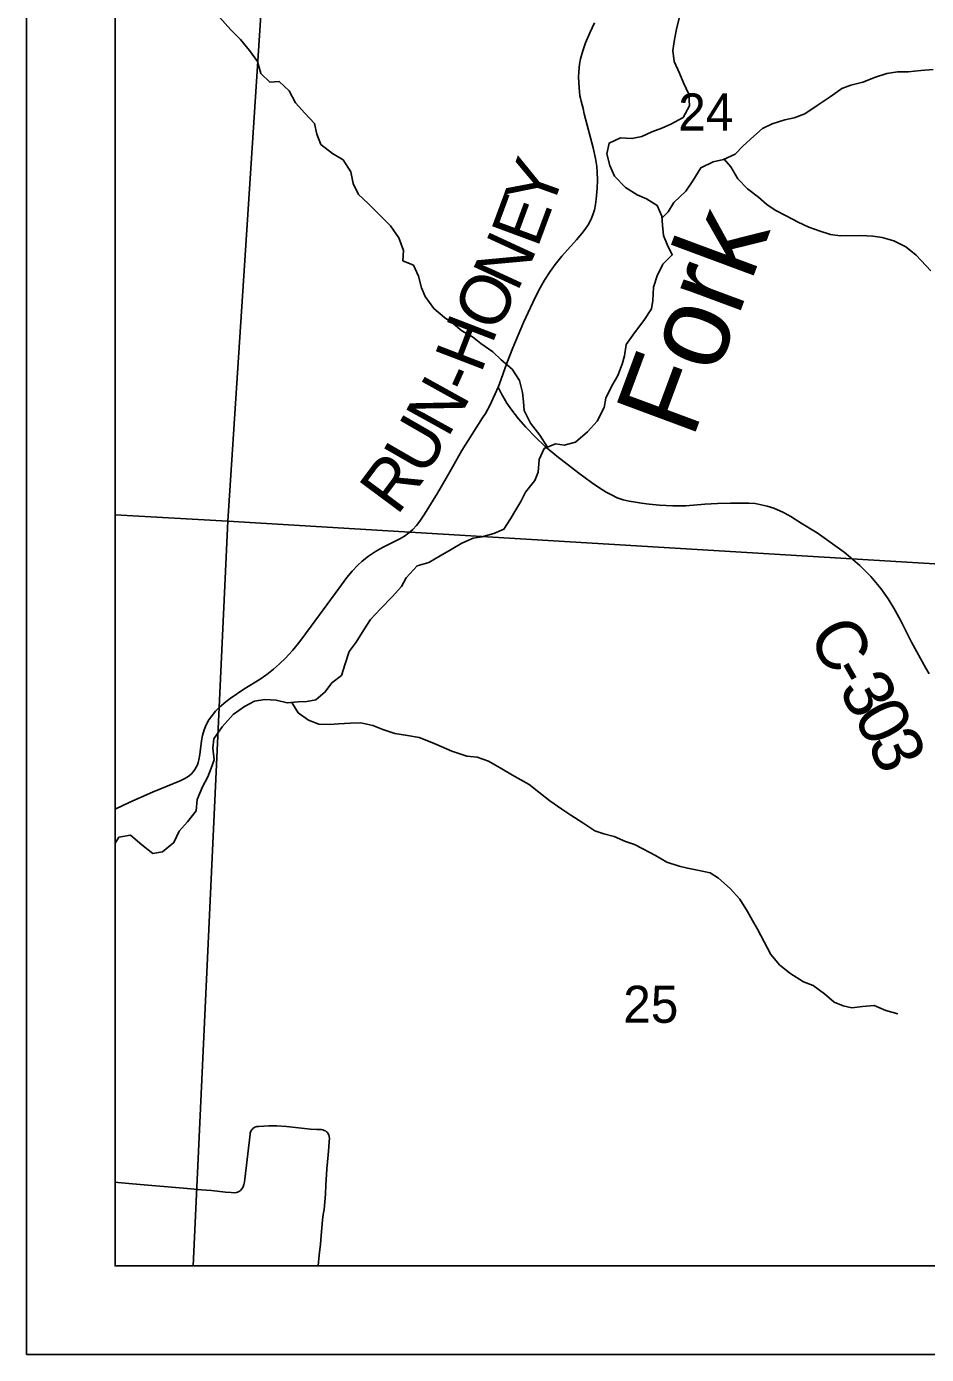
# Model space of a CAD drawing. Extents: x 0 to 34, y 0 to 22.
# Drawn here: x 2 to 3.016, y 14 to 15.5 of the extents above; entities that cross this region are included whole.
import ezdxf

# ---------------------------------------------------------------- set-up
doc = ezdxf.new("R2010")
doc.units = 0
for name, color, linetype in [('GM_X_Corporation', 7, 'Continuous'), ('GM_X_County_Road', 7, 'Continuous'), ('GM_X_County_Road_Text', 7, 'Continuous'), ('GM_X_Major_River', 7, 'Continuous'), ('GM_X_Major_River_Text', 7, 'Continuous'), ('GM_X_Minor_River', 7, 'Continuous'), ('GM_X_Section_Text', 7, 'Continuous'), ('GM_X_Township_Road', 7, 'Continuous'), ('SH_Data', 7, 'Continuous')]:
    doc.layers.add(name, color=color, linetype=linetype)

msp = doc.modelspace()

# ---------------------------------------------------------------- linework, layer by layer
at = {"layer": 'GM_X_Corporation'}
for points in [[(2.1, 19.0816), (2.1, 14.1), (3.1902, 14.1), (3.1919, 14.1255), (3.2339, 14.7735), (3.2844, 15.554), (3.3059, 15.8844), (3.3516, 16.5898), (3.3951, 17.2616), (3.507, 18.9883), (2.9513, 19.0267), (2.509, 19.0572), (2.4972, 19.0545), (2.4649, 19.0567)], [(2.1, 15.9736), (2.1, 14.9482), (2.2272, 14.9411), (2.2939, 15.964)], [(2.2939, 15.964), (3.3089, 15.8803), (3.2437, 14.8797), (2.2272, 14.9411)], [(2.1, 14.9482), (2.1, 14.1), (2.1881, 14.1), (2.2272, 14.9411)], [(2.1881, 14.1), (3.1916, 14.1), (3.2437, 14.8797), (2.2272, 14.9411)]]:
    msp.add_lwpolyline(points, close=True, dxfattribs=at)
at = {"layer": 'GM_X_County_Road'}
for points in [[(2.1, 14.6159), (2.1167, 14.6238), (2.1423, 14.6351), (2.1734, 14.648), (2.1789, 14.6507), (2.1815, 14.6522), (2.184, 14.654), (2.1862, 14.656), (2.1882, 14.6582), (2.19, 14.6606), (2.1916, 14.6632), (2.1929, 14.6659), (2.1939, 14.6687), (2.1947, 14.6717), (2.1957, 14.6777), (2.1976, 14.6932), (2.1987, 14.6993), (2.2005, 14.7054), (2.2029, 14.7112), (2.2059, 14.7168), (2.2095, 14.7219), (2.2135, 14.7268), (2.218, 14.7312), (2.225, 14.7373), (2.2299, 14.741), (2.2455, 14.7513), (2.2638, 14.7629), (2.2701, 14.7672), (2.2715, 14.7682), (2.2787, 14.7739), (2.2857, 14.78), (2.2923, 14.7865), (2.3006, 14.7956), (2.3085, 14.8052), (2.3214, 14.8226), (2.3526, 14.865), (2.3618, 14.8776), (2.3677, 14.8848), (2.3742, 14.8916), (2.3788, 14.8959), (2.3862, 14.9017), (2.394, 14.9068), (2.4021, 14.9114), (2.4215, 14.9211), (2.4268, 14.9242), (2.4317, 14.9279), (2.4362, 14.932), (2.4403, 14.9365), (2.444, 14.9414), (2.4492, 14.949), (2.464, 14.9727), (2.478, 14.9968), (2.4917, 15.0211), (2.5031, 15.0396), (2.5149, 15.0579), (2.5183, 15.063), (2.5228, 15.071), (2.5293, 15.0849), (2.5324, 15.0925), (2.5339, 15.0964), (2.5423, 15.1198), (2.5493, 15.1371), (2.5613, 15.1657), (2.5716, 15.1884), (2.5786, 15.2022), (2.5849, 15.2134), (2.5911, 15.2232), (2.5969, 15.2313), (2.6043, 15.2405), (2.6209, 15.2592), (2.627, 15.2662), (2.6308, 15.271), (2.6342, 15.2761), (2.6372, 15.2815), (2.6395, 15.2871), (2.6412, 15.293), (2.6425, 15.299), (2.6433, 15.3051), (2.6443, 15.3174), (2.6446, 15.3266), (2.6444, 15.3359), (2.6438, 15.3419), (2.6424, 15.3508), (2.6397, 15.3628), (2.6297, 15.4014), (2.6285, 15.4072), (2.6262, 15.4158), (2.6256, 15.4189), (2.6249, 15.4218), (2.6239, 15.4312), (2.6234, 15.4429), (2.6236, 15.4486), (2.6245, 15.4574), (2.6256, 15.4636), (2.6281, 15.4726), (2.6312, 15.4815), (2.636, 15.4929), (2.6413, 15.5042)], [(2.5324, 15.0925), (2.5364, 15.085), (2.5392, 15.0798), (2.5425, 15.0745), (2.5478, 15.0668), (2.5555, 15.057), (2.5637, 15.0475), (2.5746, 15.0362), (2.5855, 15.0256), (2.5989, 15.0146), (2.6237, 14.9955), (2.6379, 14.9849), (2.6464, 14.9793), (2.6547, 14.9739), (2.6604, 14.9709), (2.6671, 14.9676), (2.6736, 14.9654), (2.6805, 14.9638), (2.6876, 14.9626), (2.6945, 14.9614), (2.7031, 14.9604), (2.7148, 14.9593), (2.7299, 14.9585), (2.7445, 14.9585), (2.7659, 14.9603), (2.7804, 14.9611), (2.7948, 14.9617), (2.8072, 14.9617), (2.8158, 14.9616), (2.8227, 14.9611), (2.8294, 14.9598), (2.8362, 14.9582), (2.8439, 14.9559), (2.8546, 14.9512), (2.863, 14.9464), (2.8748, 14.9391), (2.8929, 14.9279), (2.9233, 14.9064), (2.9306, 14.9003), (2.941, 14.8912), (2.9532, 14.8789), (2.9646, 14.8652), (2.9728, 14.8536), (2.9795, 14.843), (2.9869, 14.8293), (2.9993, 14.8047), (3.0156, 14.7753), (3.0192, 14.7687)]]:
    msp.add_lwpolyline(points, dxfattribs=at)
at = {"layer": 'GM_X_Major_River'}
for points in [[(2.5635, 14.9741), (2.5741, 14.987), (2.5778, 14.9965), (2.5789, 15.0109), (2.5845, 15.0235), (2.5974, 15.0284), (2.6072, 15.027), (2.6197, 15.0304), (2.6333, 15.0423), (2.6442, 15.0541), (2.6521, 15.0696), (2.6543, 15.0802), (2.6607, 15.0932), (2.6675, 15.1057), (2.6724, 15.1186), (2.6754, 15.1281), (2.6772, 15.1406), (2.6866, 15.1539), (2.6972, 15.168), (2.7058, 15.1809), (2.7073, 15.1904), (2.708, 15.2056), (2.7121, 15.2185), (2.7185, 15.2314), (2.7291, 15.242), (2.7234, 15.2538), (2.7192, 15.264), (2.718, 15.2757), (2.7172, 15.2859), (2.7122, 15.2977), (2.7001, 15.3052), (2.6895, 15.3097), (2.6762, 15.318), (2.6641, 15.3308), (2.6587, 15.3429), (2.6553, 15.3562), (2.6579, 15.3683), (2.6707, 15.3744), (2.6836, 15.3733), (2.6949, 15.3757), (2.7059, 15.381), (2.7172, 15.3852), (2.7274, 15.3898), (2.7414, 15.3971), (2.7485, 15.4104), (2.7477, 15.4237), (2.742, 15.4365), (2.7374, 15.4471), (2.7313, 15.4603), (2.7298, 15.4728), (2.7316, 15.4854), (2.7342, 15.499), (2.7372, 15.5104)], [(2.1, 14.5774), (2.1043, 14.5843), (2.1175, 14.5867), (2.13, 14.5757), (2.1426, 14.5659), (2.1535, 14.5679), (2.1664, 14.5782), (2.1724, 14.5911), (2.1818, 14.6017), (2.1916, 14.6139), (2.1927, 14.6268), (2.1987, 14.6412), (2.2047, 14.6526), (2.2085, 14.6621), (2.2118, 14.6716), (2.2103, 14.6849), (2.2114, 14.6955), (2.2208, 14.7088), (2.2332, 14.7229), (2.2461, 14.732), (2.2574, 14.7381), (2.2691, 14.7397), (2.282, 14.739), (2.2941, 14.736), (2.3066, 14.7372), (2.3164, 14.7376), (2.3266, 14.7396), (2.3372, 14.7483), (2.3447, 14.7586), (2.3557, 14.767), (2.3598, 14.7799), (2.3643, 14.7939), (2.3722, 14.8046), (2.3809, 14.8183), (2.3884, 14.8301), (2.3997, 14.8422), (2.4129, 14.8556), (2.4235, 14.8674), (2.4287, 14.8772), (2.4412, 14.8906), (2.4544, 14.8944), (2.4672, 14.902), (2.4793, 14.9093), (2.4914, 14.9162), (2.5043, 14.9219), (2.5141, 14.9235), (2.5277, 14.9273), (2.539, 14.9323), (2.5466, 14.9437), (2.5526, 14.954), (2.5582, 14.9635), (2.5635, 14.9741)]]:
    msp.add_lwpolyline(points, dxfattribs=at)
at = {"layer": 'GM_X_Minor_River'}
for p, q in [((2.2305, 15.4964), (2.218, 15.5107)), ((2.2415, 15.4854), (2.2305, 15.4964)), ((2.2518, 15.473), (2.2415, 15.4854)), ((2.2609, 15.4605), (2.2518, 15.473)), ((2.2647, 15.4469), (2.2609, 15.4605)), ((2.2746, 15.4371), (2.2647, 15.4469)), ((2.2852, 15.4379), (2.2746, 15.4371)), ((2.2966, 15.4273), (2.2852, 15.4379)), ((2.3038, 15.4137), (2.2966, 15.4273)), ((2.3141, 15.402), (2.3038, 15.4137)), ((2.3251, 15.3903), (2.3141, 15.402)), ((2.3278, 15.3782), (2.3251, 15.3903)), ((2.3324, 15.3668), (2.3278, 15.3782)), ((2.3453, 15.3567), (2.3324, 15.3668)), ((2.3574, 15.3495), (2.3453, 15.3567)), ((2.3662, 15.3359), (2.3574, 15.3495)), ((2.7877, 15.3502), (2.7953, 15.3416)), ((2.3689, 15.3227), (2.3662, 15.3359)), ((2.7953, 15.3416), (2.8033, 15.328)), ((2.375, 15.3102), (2.3689, 15.3227)), ((2.8033, 15.328), (2.814, 15.3167)), ((2.814, 15.3167), (2.8265, 15.3073)), ((2.3856, 15.3), (2.375, 15.3102)), ((2.411, 15.2747), (2.3856, 15.3)), ((2.8265, 15.3073), (2.836, 15.299)), ((2.836, 15.299), (2.8455, 15.2926)), ((2.8455, 15.2926), (2.8576, 15.2862)), ((2.8576, 15.2862), (2.8713, 15.2791)), ((2.4202, 15.2611), (2.411, 15.2747)), ((2.8713, 15.2791), (2.8834, 15.2734)), ((2.8834, 15.2734), (2.8963, 15.2689)), ((2.4255, 15.2471), (2.4202, 15.2611)), ((2.8963, 15.2689), (2.908, 15.2652)), ((2.908, 15.2652), (2.9186, 15.2637)), ((2.9186, 15.2637), (2.9421, 15.2638)), ((2.9421, 15.2638), (2.9557, 15.2631)), ((2.9557, 15.2631), (2.9663, 15.2617)), ((2.9663, 15.2617), (2.9792, 15.2579)), ((2.9792, 15.2579), (2.9928, 15.2512)), ((2.4248, 15.2354), (2.4255, 15.2471)), ((2.9928, 15.2512), (3.0046, 15.2418)), ((3.0046, 15.2418), (3.0213, 15.224)), ((2.4369, 15.2305), (2.4248, 15.2354)), ((2.4427, 15.218), (2.4369, 15.2305)), ((2.4461, 15.2048), (2.4427, 15.218)), ((2.4503, 15.1949), (2.4461, 15.2048)), ((2.4598, 15.1813), (2.4503, 15.1949)), ((2.472, 15.1711), (2.4598, 15.1813)), ((2.4822, 15.164), (2.472, 15.1711)), ((2.4917, 15.1561), (2.4822, 15.164)), ((2.5035, 15.1493), (2.4917, 15.1561)), ((2.5129, 15.1418), (2.5035, 15.1493)), ((2.5266, 15.1324), (2.5129, 15.1418)), ((2.5361, 15.1233), (2.5266, 15.1324)), ((2.5483, 15.1131), (2.5361, 15.1233)), ((2.5566, 15.1003), (2.5483, 15.1131)), ((2.5601, 15.0866), (2.5566, 15.1003)), ((2.5612, 15.076), (2.5601, 15.0866)), ((2.562, 15.0662), (2.5612, 15.076)), ((2.5689, 15.0518), (2.562, 15.0662)), ((2.5795, 15.0382), (2.5689, 15.0518)), ((2.5884, 15.025), (2.5795, 15.0382)), ((2.2996, 14.7365), (2.3066, 14.7247)), ((2.3066, 14.7247), (2.3184, 14.7164)), ((2.3184, 14.7164), (2.3301, 14.7119)), ((2.3301, 14.7119), (2.3423, 14.7116)), ((2.3423, 14.7116), (2.3521, 14.7124)), ((2.3521, 14.7124), (2.3657, 14.7132)), ((2.3657, 14.7132), (2.3775, 14.7133)), ((2.3775, 14.7133), (2.3911, 14.7103)), ((2.3911, 14.7103), (2.4025, 14.7058)), ((2.4025, 14.7058), (2.4157, 14.7013)), ((2.4157, 14.7013), (2.4301, 14.6991)), ((2.4301, 14.6991), (2.4434, 14.6969)), ((2.4434, 14.6969), (2.4578, 14.6913)), ((2.4578, 14.6913), (2.468, 14.6868)), ((2.468, 14.6868), (2.4801, 14.6815)), ((2.4801, 14.6815), (2.4972, 14.6759)), ((2.4972, 14.6759), (2.5089, 14.6748)), ((2.5089, 14.6748), (2.5218, 14.67)), ((2.5218, 14.67), (2.5366, 14.6613)), ((2.5366, 14.6613), (2.5487, 14.6542)), ((2.5487, 14.6542), (2.5677, 14.6436)), ((2.5677, 14.6436), (2.5783, 14.6353)), ((2.5783, 14.6353), (2.5908, 14.6255)), ((2.5908, 14.6255), (2.6045, 14.6158)), ((2.6045, 14.6158), (2.6147, 14.609)), ((2.6147, 14.609), (2.628, 14.6003)), ((2.628, 14.6003), (2.6417, 14.5913)), ((2.6417, 14.5913), (2.6519, 14.5879)), ((2.6519, 14.5879), (2.6637, 14.5849)), ((2.6637, 14.5849), (2.6765, 14.5793)), ((2.6765, 14.5793), (2.6864, 14.5759)), ((2.6864, 14.5759), (2.6959, 14.5711)), ((2.6959, 14.5711), (2.7103, 14.5635)), ((2.7103, 14.5635), (2.7232, 14.556)), ((2.7232, 14.556), (2.7368, 14.5515)), ((2.7368, 14.5515), (2.7463, 14.5493)), ((2.7463, 14.5493), (2.7576, 14.5471)), ((2.7576, 14.5471), (2.772, 14.5441)), ((2.772, 14.5441), (2.7815, 14.5381)), ((2.7815, 14.5381), (2.7944, 14.5264)), ((2.7944, 14.5264), (2.8055, 14.5143)), ((2.8055, 14.5143), (2.8142, 14.5003)), ((2.8142, 14.5003), (2.8199, 14.4901)), ((2.8199, 14.4901), (2.8253, 14.4803)), ((2.8253, 14.4803), (2.8405, 14.4516)), ((2.8405, 14.4516), (2.8504, 14.4399)), ((2.8504, 14.4399), (2.8621, 14.4308)), ((2.8621, 14.4308), (2.8773, 14.421)), ((2.8773, 14.421), (2.8883, 14.4169)), ((2.8883, 14.4169), (2.9012, 14.4075)), ((2.9012, 14.4075), (2.9118, 14.3981)), ((2.9118, 14.3981), (2.9221, 14.3936)), ((2.9221, 14.3936), (2.9319, 14.3917)), ((2.9319, 14.3917), (2.944, 14.3929)), ((2.944, 14.3929), (2.9573, 14.3941)), ((2.9573, 14.3941), (2.9705, 14.3885)), ((2.9705, 14.3885), (2.9838, 14.3847))]:
    msp.add_line(p, q, dxfattribs=at)
msp.add_lwpolyline([(2.7174, 15.2834), (2.7244, 15.2905), (2.7308, 15.3012), (2.7443, 15.3141), (2.7523, 15.3255), (2.7613, 15.3403), (2.7753, 15.3472), (2.787, 15.3499), (2.8002, 15.3557), (2.8093, 15.3652), (2.8213, 15.3762), (2.8311, 15.3846), (2.8421, 15.39), (2.8561, 15.3946), (2.8667, 15.3969), (2.8788, 15.4015), (2.8939, 15.4114), (2.9075, 15.4206), (2.9207, 15.4301), (2.9309, 15.4336), (2.9445, 15.437), (2.9585, 15.4428), (2.9713, 15.447), (2.9834, 15.4486), (2.9956, 15.4486), (3.0099, 15.4502), (3.0239, 15.4514)], dxfattribs=at)
at = {"layer": 'GM_X_Township_Road'}
msp.add_lwpolyline([(2.3293, 14.1), (2.3305, 14.1122), (2.3318, 14.1245), (2.3327, 14.1342), (2.3343, 14.1518), (2.3351, 14.158), (2.336, 14.1638), (2.3374, 14.1812), (2.338, 14.1916), (2.3387, 14.2034), (2.3391, 14.2098), (2.3404, 14.2256), (2.3412, 14.234), (2.3418, 14.2407), (2.342, 14.2438), (2.3418, 14.2463), (2.3414, 14.2482), (2.3407, 14.2493), (2.3397, 14.2507), (2.3387, 14.2516), (2.3374, 14.2525), (2.3361, 14.2531), (2.3347, 14.2536), (2.3329, 14.254), (2.3309, 14.2541), (2.3278, 14.2541), (2.3206, 14.2546), (2.3038, 14.2564), (2.2935, 14.2574), (2.2825, 14.2582), (2.2736, 14.2581), (2.2622, 14.2574), (2.2612, 14.2574), (2.2602, 14.2573), (2.259, 14.257), (2.2579, 14.2566), (2.2568, 14.256), (2.2556, 14.2551), (2.2546, 14.2541), (2.2539, 14.2532), (2.2534, 14.2523), (2.2529, 14.2511), (2.2526, 14.2499), (2.2524, 14.2487), (2.2466, 14.1981), (2.246, 14.1949), (2.2454, 14.192), (2.2445, 14.1894), (2.2431, 14.1871), (2.2414, 14.185), (2.2395, 14.1836), (2.2371, 14.1828), (2.2343, 14.1827), (2.231, 14.1828), (2.2245, 14.1834), (2.2088, 14.185), (2.1977, 14.186), (2.1771, 14.1877), (2.1413, 14.1907), (2.1195, 14.1927), (2.1031, 14.1943), (2.1, 14.1945)], dxfattribs=at)
at = {"layer": 'SH_Data'}
for p, q in [((2, 21), (2, 14)), ((2.1, 20.9), (2.1, 14.1)), ((2.1, 14.1), (8.9, 14.1)), ((2.1, 14.1), (2.1, 14.1)), ((2, 14), (9, 14))]:
    msp.add_line(p, q, dxfattribs=at)

# ---------------------------------------------------------------- texts
at = {"layer": 'GM_X_County_Road_Text'}
for s, rotation, p in [('Y', 70.3131, (2.5918, 15.2893)), ('E', 69.6477, (2.5768, 15.2488)), ('N', 65.2103, (2.554, 15.199)), ('O', 63.0684, (2.5303, 15.1523)), ('H', 68.9626, (2.513, 15.107)), ('N', 61.0033, (2.4756, 15.0342)), ('-', 65.9203, (2.5022, 15.0827)), ('U', 60.0583, (2.4502, 14.99)), ('R', 53.3557, (2.4183, 14.9465)), ('C', 299.7294, (2.8815, 14.8122)), ('-', 299.6074, (2.9046, 14.7717)), ('3', 299.1911, (2.9161, 14.7515)), ('0', 297.5588, (2.933, 14.7213)), ('3', 294.4655, (2.9488, 14.691))]:
    msp.add_text(s, height=0.0568, rotation=rotation, dxfattribs=at).set_placement(p)
at = {"layer": 'GM_X_Major_River_Text'}
msp.add_text('Fork', height=0.0947, rotation=69.6047, dxfattribs=at).set_placement((2.752, 15.0327))
at = {"layer": 'GM_X_Section_Text'}
for s, p in [('24', (2.7359, 15.3825)), ('25', (2.6738, 14.3746))]:
    msp.add_text(s, height=0.04186, rotation=0, dxfattribs=at).set_placement(p)

doc.saveas('drawing.dxf')
